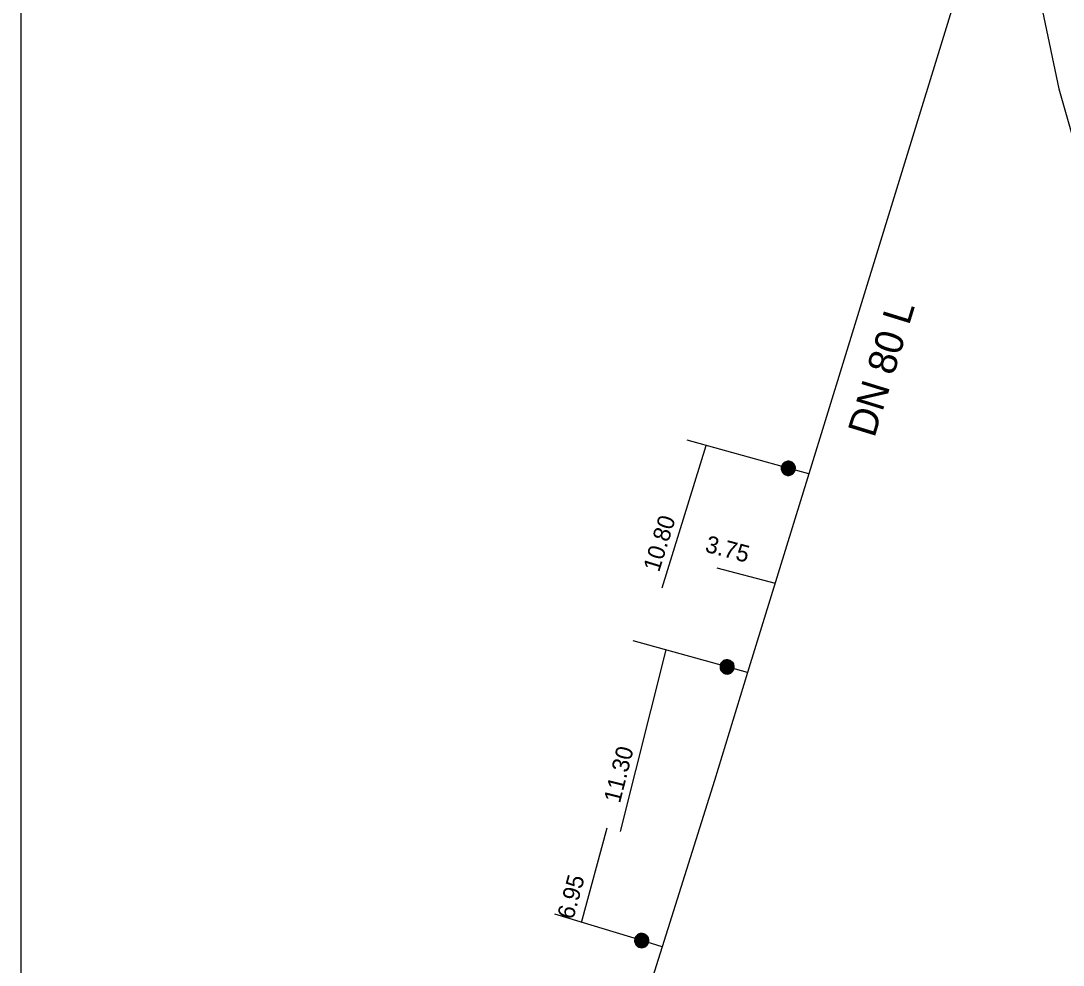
# Model space of a CAD drawing. Extents: x -820257 to -819974, y -1070894 to -1070484.
# Drawn here: x -820256.8 to -820183, y -1070688.6 to -1070621.8 of the extents above; entities that cross this region are included whole.
import ezdxf

# ---------------------------------------------------------------- set-up
doc = ezdxf.new("R2010")
doc.units = 0
for name, color, linetype in [('Default', 7, 'Continuous'), ('Oměrka vodovodu', 7, 'Continuous'), ('Oměrka-text', 7, 'Continuous'), ('Přípojka vodovodu', 7, 'Continuous'), ('Přípojkový uzávěr', 7, 'Continuous'), ('Roz-řad', 7, 'Continuous'), ('Roz-řad-popis základní', 7, 'Continuous')]:
    doc.layers.add(name, color=color, linetype=linetype)

msp = doc.modelspace()

# ---------------------------------------------------------------- linework, layer by layer
at = {"layer": 'Default'}
msp.add_lwpolyline([(-819975.603, -1070484.403), (-820256.81, -1070484.403), (-820256.81, -1070893.932)], dxfattribs=at)
at = {"layer": 'Oměrka vodovodu'}
for p, q in [((-820211.408, -1070661.903), (-820208.285, -1070651.83)), ((-820207.542, -1070660.475), (-820203.412, -1070661.564)), ((-820211.154, -1070666.294), (-820214.389, -1070679.146)), ((-820217.121, -1070685.573), (-820215.292, -1070678.876))]:
    msp.add_line(p, q, dxfattribs=at)
at = {"layer": 'Přípojka vodovodu'}
for points in [[(-820201.034, -1070653.842), (-820202.479, -1070653.441), (-820209.648, -1070651.452)], [(-820205.362, -1070667.895), (-820206.808, -1070667.495), (-820213.456, -1070665.657)], [(-820211.419, -1070687.296), (-820212.855, -1070686.862), (-820218.999, -1070685.006)]]:
    msp.add_lwpolyline(points, dxfattribs=at)
at = {"layer": 'Přípojkový uzávěr'}
for points in [[(-820202.345, -1070652.959), (-820202.224, -1070652.993), (-820202.126, -1070653.087), (-820202.028, -1070653.181), (-820201.995, -1070653.315), (-820201.962, -1070653.449), (-820201.997, -1070653.575), (-820202.032, -1070653.7), (-820202.127, -1070653.797), (-820202.222, -1070653.894), (-820202.355, -1070653.926), (-820202.487, -1070653.957), (-820202.613, -1070653.923), (-820202.737, -1070653.888), (-820202.835, -1070653.793), (-820202.932, -1070653.697), (-820202.963, -1070653.565), (-820202.995, -1070653.433), (-820202.96, -1070653.308), (-820202.925, -1070653.182), (-820202.829, -1070653.084), (-820202.732, -1070652.986), (-820202.599, -1070652.955), (-820202.467, -1070652.925), (-820202.345, -1070652.959)], [(-820202.358, -1070653.004), (-820202.468, -1070652.974), (-820202.588, -1070653.001), (-820202.708, -1070653.028), (-820202.796, -1070653.117), (-820202.884, -1070653.206), (-820202.915, -1070653.32), (-820202.947, -1070653.434), (-820202.918, -1070653.553), (-820202.89, -1070653.673), (-820202.801, -1070653.76), (-820202.713, -1070653.846), (-820202.6, -1070653.877), (-820202.486, -1070653.909), (-820202.366, -1070653.88), (-820202.246, -1070653.852), (-820202.16, -1070653.764), (-820202.073, -1070653.676), (-820202.042, -1070653.563), (-820202.01, -1070653.448), (-820202.04, -1070653.327), (-820202.07, -1070653.205), (-820202.159, -1070653.12), (-820202.248, -1070653.035), (-820202.358, -1070653.004)], [(-820202.367, -1070653.037), (-820202.265, -1070653.065), (-820202.183, -1070653.144), (-820202.101, -1070653.223), (-820202.073, -1070653.335), (-820202.046, -1070653.448), (-820202.075, -1070653.553), (-820202.104, -1070653.658), (-820202.184, -1070653.74), (-820202.263, -1070653.821), (-820202.374, -1070653.847), (-820202.486, -1070653.874), (-820202.591, -1070653.844), (-820202.695, -1070653.815), (-820202.777, -1070653.736), (-820202.859, -1070653.656), (-820202.885, -1070653.545), (-820202.911, -1070653.434), (-820202.882, -1070653.329), (-820202.853, -1070653.223), (-820202.772, -1070653.141), (-820202.691, -1070653.059), (-820202.58, -1070653.034), (-820202.469, -1070653.009), (-820202.367, -1070653.037)], [(-820202.379, -1070653.079), (-820202.53, -1070653.038), (-820202.664, -1070653.114), (-820202.798, -1070653.191), (-820202.84, -1070653.341), (-820202.882, -1070653.491), (-820202.805, -1070653.626), (-820202.728, -1070653.761), (-820202.58, -1070653.802), (-820202.429, -1070653.844), (-820202.294, -1070653.768), (-820202.159, -1070653.691), (-820202.117, -1070653.542), (-820202.076, -1070653.392), (-820202.151, -1070653.257), (-820202.227, -1070653.121), (-820202.379, -1070653.079)], [(-820202.391, -1070653.124), (-820202.259, -1070653.16), (-820202.193, -1070653.278), (-820202.127, -1070653.396), (-820202.163, -1070653.527), (-820202.199, -1070653.659), (-820202.318, -1070653.726), (-820202.436, -1070653.792), (-820202.567, -1070653.756), (-820202.699, -1070653.719), (-820202.765, -1070653.601), (-820202.832, -1070653.483), (-820202.795, -1070653.352), (-820202.759, -1070653.221), (-820202.641, -1070653.154), (-820202.523, -1070653.087), (-820202.391, -1070653.124)], [(-820202.402, -1070653.162), (-820202.518, -1070653.13), (-820202.622, -1070653.188), (-820202.725, -1070653.247), (-820202.757, -1070653.363), (-820202.789, -1070653.478), (-820202.731, -1070653.582), (-820202.672, -1070653.686), (-820202.556, -1070653.718), (-820202.441, -1070653.75), (-820202.337, -1070653.691), (-820202.233, -1070653.632), (-820202.201, -1070653.517), (-820202.169, -1070653.402), (-820202.227, -1070653.298), (-820202.286, -1070653.194), (-820202.402, -1070653.162)], [(-820202.412, -1070653.2), (-820202.311, -1070653.228), (-820202.26, -1070653.318), (-820202.21, -1070653.408), (-820202.238, -1070653.508), (-820202.265, -1070653.608), (-820202.356, -1070653.659), (-820202.446, -1070653.709), (-820202.546, -1070653.682), (-820202.645, -1070653.654), (-820202.696, -1070653.564), (-820202.747, -1070653.474), (-820202.72, -1070653.375), (-820202.692, -1070653.274), (-820202.602, -1070653.223), (-820202.513, -1070653.172), (-820202.412, -1070653.2)], [(-820202.425, -1070653.245), (-820202.506, -1070653.222), (-820202.579, -1070653.263), (-820202.652, -1070653.305), (-820202.675, -1070653.386), (-820202.697, -1070653.467), (-820202.656, -1070653.54), (-820202.615, -1070653.613), (-820202.533, -1070653.636), (-820202.452, -1070653.659), (-820202.379, -1070653.617), (-820202.306, -1070653.576), (-820202.283, -1070653.495), (-820202.261, -1070653.413), (-820202.302, -1070653.34), (-820202.343, -1070653.267), (-820202.425, -1070653.245)], [(-820202.434, -1070653.278), (-820202.366, -1070653.297), (-820202.332, -1070653.357), (-820202.298, -1070653.418), (-820202.317, -1070653.485), (-820202.335, -1070653.553), (-820202.396, -1070653.587), (-820202.457, -1070653.621), (-820202.524, -1070653.603), (-820202.592, -1070653.584), (-820202.626, -1070653.523), (-820202.66, -1070653.463), (-820202.641, -1070653.395), (-820202.622, -1070653.328), (-820202.562, -1070653.293), (-820202.502, -1070653.259), (-820202.434, -1070653.278)], [(-820202.446, -1070653.32), (-820202.495, -1070653.306), (-820202.54, -1070653.332), (-820202.585, -1070653.358), (-820202.599, -1070653.407), (-820202.613, -1070653.457), (-820202.587, -1070653.502), (-820202.562, -1070653.548), (-820202.512, -1070653.561), (-820202.462, -1070653.575), (-820202.417, -1070653.55), (-820202.372, -1070653.524), (-820202.358, -1070653.474), (-820202.344, -1070653.424), (-820202.369, -1070653.379), (-820202.395, -1070653.334), (-820202.446, -1070653.32)], [(-820202.458, -1070653.366), (-820202.426, -1070653.374), (-820202.41, -1070653.402), (-820202.395, -1070653.43), (-820202.404, -1070653.462), (-820202.412, -1070653.493), (-820202.44, -1070653.509), (-820202.468, -1070653.525), (-820202.5, -1070653.516), (-820202.531, -1070653.507), (-820202.547, -1070653.479), (-820202.563, -1070653.451), (-820202.554, -1070653.42), (-820202.545, -1070653.388), (-820202.517, -1070653.372), (-820202.489, -1070653.357), (-820202.458, -1070653.366)], [(-820202.466, -1070653.396), (-820202.485, -1070653.39), (-820202.502, -1070653.4), (-820202.519, -1070653.409), (-820202.524, -1070653.428), (-820202.529, -1070653.447), (-820202.52, -1070653.464), (-820202.51, -1070653.481), (-820202.492, -1070653.486), (-820202.472, -1070653.491), (-820202.456, -1070653.482), (-820202.439, -1070653.472), (-820202.434, -1070653.453), (-820202.428, -1070653.434), (-820202.438, -1070653.418), (-820202.447, -1070653.401), (-820202.466, -1070653.396)], [(-820206.675, -1070667.013), (-820206.554, -1070667.047), (-820206.456, -1070667.141), (-820206.357, -1070667.235), (-820206.324, -1070667.369), (-820206.291, -1070667.503), (-820206.326, -1070667.629), (-820206.361, -1070667.754), (-820206.456, -1070667.851), (-820206.551, -1070667.948), (-820206.683, -1070667.98), (-820206.816, -1070668.012), (-820206.942, -1070667.977), (-820207.066, -1070667.943), (-820207.164, -1070667.847), (-820207.261, -1070667.752), (-820207.293, -1070667.62), (-820207.324, -1070667.488), (-820207.29, -1070667.363), (-820207.255, -1070667.236), (-820207.158, -1070667.138), (-820207.061, -1070667.04), (-820206.929, -1070667.01), (-820206.797, -1070666.98), (-820206.675, -1070667.013)], [(-820206.688, -1070667.058), (-820206.798, -1070667.028), (-820206.918, -1070667.055), (-820207.038, -1070667.083), (-820207.125, -1070667.172), (-820207.213, -1070667.261), (-820207.245, -1070667.375), (-820207.276, -1070667.488), (-820207.247, -1070667.608), (-820207.219, -1070667.728), (-820207.13, -1070667.814), (-820207.042, -1070667.901), (-820206.929, -1070667.932), (-820206.815, -1070667.963), (-820206.695, -1070667.935), (-820206.575, -1070667.906), (-820206.489, -1070667.818), (-820206.403, -1070667.73), (-820206.371, -1070667.617), (-820206.34, -1070667.502), (-820206.37, -1070667.381), (-820206.4, -1070667.259), (-820206.489, -1070667.174), (-820206.577, -1070667.089), (-820206.688, -1070667.058)], [(-820206.697, -1070667.091), (-820206.595, -1070667.12), (-820206.513, -1070667.198), (-820206.431, -1070667.277), (-820206.403, -1070667.389), (-820206.375, -1070667.502), (-820206.404, -1070667.607), (-820206.433, -1070667.712), (-820206.513, -1070667.794), (-820206.592, -1070667.875), (-820206.703, -1070667.902), (-820206.815, -1070667.928), (-820206.92, -1070667.899), (-820207.024, -1070667.87), (-820207.106, -1070667.79), (-820207.188, -1070667.71), (-820207.214, -1070667.6), (-820207.241, -1070667.489), (-820207.212, -1070667.384), (-820207.182, -1070667.278), (-820207.101, -1070667.196), (-820207.021, -1070667.114), (-820206.909, -1070667.089), (-820206.798, -1070667.063), (-820206.697, -1070667.091)], [(-820206.709, -1070667.134), (-820206.859, -1070667.092), (-820206.994, -1070667.169), (-820207.128, -1070667.246), (-820207.169, -1070667.396), (-820207.211, -1070667.546), (-820207.134, -1070667.68), (-820207.057, -1070667.815), (-820206.909, -1070667.857), (-820206.758, -1070667.898), (-820206.623, -1070667.822), (-820206.488, -1070667.745), (-820206.447, -1070667.596), (-820206.405, -1070667.446), (-820206.481, -1070667.311), (-820206.557, -1070667.176), (-820206.709, -1070667.134)], [(-820206.721, -1070667.178), (-820206.589, -1070667.214), (-820206.522, -1070667.332), (-820206.456, -1070667.45), (-820206.492, -1070667.582), (-820206.529, -1070667.713), (-820206.647, -1070667.78), (-820206.765, -1070667.847), (-820206.896, -1070667.81), (-820207.028, -1070667.774), (-820207.094, -1070667.656), (-820207.161, -1070667.538), (-820207.125, -1070667.407), (-820207.088, -1070667.275), (-820206.971, -1070667.208), (-820206.853, -1070667.141), (-820206.721, -1070667.178)], [(-820206.732, -1070667.216), (-820206.847, -1070667.184), (-820206.951, -1070667.243), (-820207.055, -1070667.302), (-820207.087, -1070667.417), (-820207.119, -1070667.533), (-820207.06, -1070667.636), (-820207.001, -1070667.74), (-820206.885, -1070667.772), (-820206.77, -1070667.804), (-820206.666, -1070667.745), (-820206.562, -1070667.686), (-820206.53, -1070667.571), (-820206.499, -1070667.456), (-820206.557, -1070667.352), (-820206.615, -1070667.248), (-820206.732, -1070667.216)], [(-820206.742, -1070667.254), (-820206.641, -1070667.282), (-820206.59, -1070667.372), (-820206.539, -1070667.462), (-820206.567, -1070667.562), (-820206.595, -1070667.662), (-820206.685, -1070667.713), (-820206.775, -1070667.764), (-820206.875, -1070667.736), (-820206.974, -1070667.709), (-820207.025, -1070667.619), (-820207.077, -1070667.529), (-820207.049, -1070667.429), (-820207.021, -1070667.329), (-820206.932, -1070667.278), (-820206.842, -1070667.226), (-820206.742, -1070667.254)], [(-820206.754, -1070667.299), (-820206.835, -1070667.276), (-820206.908, -1070667.318), (-820206.981, -1070667.359), (-820207.004, -1070667.441), (-820207.026, -1070667.522), (-820206.985, -1070667.595), (-820206.944, -1070667.668), (-820206.862, -1070667.691), (-820206.781, -1070667.713), (-820206.708, -1070667.672), (-820206.635, -1070667.63), (-820206.612, -1070667.549), (-820206.59, -1070667.467), (-820206.631, -1070667.394), (-820206.673, -1070667.321), (-820206.754, -1070667.299)], [(-820206.763, -1070667.332), (-820206.696, -1070667.351), (-820206.661, -1070667.411), (-820206.627, -1070667.472), (-820206.646, -1070667.54), (-820206.665, -1070667.607), (-820206.725, -1070667.642), (-820206.786, -1070667.676), (-820206.853, -1070667.657), (-820206.921, -1070667.638), (-820206.955, -1070667.578), (-820206.989, -1070667.518), (-820206.971, -1070667.45), (-820206.952, -1070667.382), (-820206.891, -1070667.348), (-820206.831, -1070667.314), (-820206.763, -1070667.332)], [(-820206.775, -1070667.375), (-820206.825, -1070667.361), (-820206.87, -1070667.387), (-820206.915, -1070667.412), (-820206.928, -1070667.462), (-820206.942, -1070667.512), (-820206.917, -1070667.557), (-820206.891, -1070667.602), (-820206.842, -1070667.616), (-820206.791, -1070667.63), (-820206.746, -1070667.604), (-820206.701, -1070667.579), (-820206.687, -1070667.529), (-820206.674, -1070667.479), (-820206.699, -1070667.434), (-820206.724, -1070667.389), (-820206.775, -1070667.375)], [(-820206.787, -1070667.42), (-820206.755, -1070667.429), (-820206.74, -1070667.456), (-820206.724, -1070667.484), (-820206.733, -1070667.516), (-820206.742, -1070667.547), (-820206.769, -1070667.563), (-820206.797, -1070667.579), (-820206.829, -1070667.57), (-820206.86, -1070667.562), (-820206.876, -1070667.534), (-820206.892, -1070667.505), (-820206.884, -1070667.474), (-820206.875, -1070667.442), (-820206.847, -1070667.427), (-820206.819, -1070667.411), (-820206.787, -1070667.42)], [(-820206.796, -1070667.45), (-820206.815, -1070667.445), (-820206.831, -1070667.454), (-820206.848, -1070667.463), (-820206.853, -1070667.483), (-820206.859, -1070667.502), (-820206.849, -1070667.518), (-820206.84, -1070667.535), (-820206.821, -1070667.54), (-820206.802, -1070667.546), (-820206.785, -1070667.536), (-820206.768, -1070667.527), (-820206.763, -1070667.508), (-820206.758, -1070667.488), (-820206.767, -1070667.472), (-820206.777, -1070667.455), (-820206.796, -1070667.45)], [(-820212.711, -1070686.383), (-820212.59, -1070686.42), (-820212.494, -1070686.516), (-820212.398, -1070686.612), (-820212.368, -1070686.747), (-820212.338, -1070686.882), (-820212.376, -1070687.007), (-820212.414, -1070687.131), (-820212.511, -1070687.226), (-820212.609, -1070687.321), (-820212.742, -1070687.35), (-820212.875, -1070687.378), (-820213, -1070687.34), (-820213.124, -1070687.303), (-820213.219, -1070687.205), (-820213.314, -1070687.108), (-820213.342, -1070686.975), (-820213.371, -1070686.842), (-820213.334, -1070686.718), (-820213.296, -1070686.593), (-820213.197, -1070686.497), (-820213.098, -1070686.401), (-820212.965, -1070686.374), (-820212.832, -1070686.347), (-820212.711, -1070686.383)], [(-820212.724, -1070686.428), (-820212.834, -1070686.395), (-820212.954, -1070686.42), (-820213.075, -1070686.444), (-820213.165, -1070686.531), (-820213.254, -1070686.618), (-820213.289, -1070686.731), (-820213.323, -1070686.844), (-820213.297, -1070686.964), (-820213.271, -1070687.085), (-820213.185, -1070687.173), (-820213.098, -1070687.262), (-820212.986, -1070687.296), (-820212.873, -1070687.33), (-820212.752, -1070687.304), (-820212.632, -1070687.278), (-820212.543, -1070687.192), (-820212.455, -1070687.106), (-820212.421, -1070686.994), (-820212.387, -1070686.88), (-820212.414, -1070686.758), (-820212.441, -1070686.635), (-820212.528, -1070686.548), (-820212.615, -1070686.461), (-820212.724, -1070686.428)], [(-820212.734, -1070686.461), (-820212.633, -1070686.491), (-820212.553, -1070686.572), (-820212.473, -1070686.653), (-820212.447, -1070686.765), (-820212.422, -1070686.878), (-820212.454, -1070686.984), (-820212.485, -1070687.088), (-820212.567, -1070687.167), (-820212.648, -1070687.247), (-820212.76, -1070687.271), (-820212.872, -1070687.295), (-820212.976, -1070687.263), (-820213.08, -1070687.232), (-820213.16, -1070687.15), (-820213.24, -1070687.068), (-820213.264, -1070686.957), (-820213.287, -1070686.846), (-820213.256, -1070686.741), (-820213.224, -1070686.636), (-820213.141, -1070686.556), (-820213.058, -1070686.476), (-820212.947, -1070686.453), (-820212.835, -1070686.43), (-820212.734, -1070686.461)], [(-820212.747, -1070686.503), (-820212.897, -1070686.458), (-820213.033, -1070686.531), (-820213.169, -1070686.605), (-820213.214, -1070686.754), (-820213.259, -1070686.903), (-820213.185, -1070687.039), (-820213.112, -1070687.176), (-820212.964, -1070687.221), (-820212.815, -1070687.266), (-820212.678, -1070687.193), (-820212.541, -1070687.12), (-820212.496, -1070686.971), (-820212.451, -1070686.822), (-820212.524, -1070686.685), (-820212.596, -1070686.548), (-820212.747, -1070686.503)], [(-820212.761, -1070686.547), (-820212.629, -1070686.586), (-820212.566, -1070686.706), (-820212.502, -1070686.825), (-820212.541, -1070686.956), (-820212.581, -1070687.086), (-820212.7, -1070687.15), (-820212.82, -1070687.214), (-820212.95, -1070687.175), (-820213.081, -1070687.135), (-820213.145, -1070687.016), (-820213.209, -1070686.896), (-820213.17, -1070686.766), (-820213.13, -1070686.635), (-820213.011, -1070686.571), (-820212.891, -1070686.507), (-820212.761, -1070686.547)], [(-820212.772, -1070686.585), (-820212.887, -1070686.55), (-820212.992, -1070686.606), (-820213.097, -1070686.663), (-820213.132, -1070686.777), (-820213.166, -1070686.892), (-820213.11, -1070686.997), (-820213.054, -1070687.102), (-820212.939, -1070687.137), (-820212.824, -1070687.172), (-820212.719, -1070687.115), (-820212.614, -1070687.059), (-820212.579, -1070686.944), (-820212.545, -1070686.83), (-820212.601, -1070686.725), (-820212.656, -1070686.619), (-820212.772, -1070686.585)], [(-820212.783, -1070686.623), (-820212.682, -1070686.653), (-820212.634, -1070686.744), (-820212.586, -1070686.835), (-820212.616, -1070686.935), (-820212.646, -1070687.034), (-820212.737, -1070687.083), (-820212.828, -1070687.131), (-820212.928, -1070687.101), (-820213.026, -1070687.071), (-820213.075, -1070686.98), (-820213.124, -1070686.889), (-820213.094, -1070686.79), (-820213.064, -1070686.691), (-820212.974, -1070686.641), (-820212.883, -1070686.592), (-820212.783, -1070686.623)], [(-820212.796, -1070686.667), (-820212.877, -1070686.643), (-820212.951, -1070686.682), (-820213.025, -1070686.722), (-820213.05, -1070686.803), (-820213.074, -1070686.883), (-820213.034, -1070686.957), (-820212.995, -1070687.031), (-820212.914, -1070687.056), (-820212.833, -1070687.08), (-820212.759, -1070687.041), (-820212.685, -1070687.001), (-820212.661, -1070686.92), (-820212.636, -1070686.839), (-820212.676, -1070686.765), (-820212.715, -1070686.691), (-820212.796, -1070686.667)], [(-820212.806, -1070686.7), (-820212.739, -1070686.72), (-820212.706, -1070686.782), (-820212.673, -1070686.843), (-820212.694, -1070686.91), (-820212.714, -1070686.977), (-820212.776, -1070687.01), (-820212.837, -1070687.043), (-820212.904, -1070687.023), (-820212.971, -1070687.002), (-820213.004, -1070686.941), (-820213.037, -1070686.88), (-820213.016, -1070686.813), (-820212.996, -1070686.745), (-820212.935, -1070686.713), (-820212.874, -1070686.68), (-820212.806, -1070686.7)], [(-820212.819, -1070686.742), (-820212.869, -1070686.727), (-820212.914, -1070686.752), (-820212.959, -1070686.776), (-820212.974, -1070686.826), (-820212.989, -1070686.875), (-820212.965, -1070686.921), (-820212.94, -1070686.967), (-820212.891, -1070686.982), (-820212.841, -1070686.997), (-820212.796, -1070686.972), (-820212.75, -1070686.948), (-820212.735, -1070686.898), (-820212.72, -1070686.849), (-820212.744, -1070686.803), (-820212.769, -1070686.757), (-820212.819, -1070686.742)], [(-820212.833, -1070686.787), (-820212.801, -1070686.797), (-820212.786, -1070686.825), (-820212.771, -1070686.853), (-820212.78, -1070686.884), (-820212.79, -1070686.915), (-820212.818, -1070686.931), (-820212.846, -1070686.946), (-820212.878, -1070686.937), (-820212.909, -1070686.927), (-820212.924, -1070686.899), (-820212.939, -1070686.87), (-820212.93, -1070686.839), (-820212.92, -1070686.807), (-820212.892, -1070686.793), (-820212.863, -1070686.778), (-820212.833, -1070686.787)], [(-820212.842, -1070686.817), (-820212.86, -1070686.811), (-820212.877, -1070686.82), (-820212.894, -1070686.829), (-820212.9, -1070686.848), (-820212.906, -1070686.867), (-820212.897, -1070686.884), (-820212.887, -1070686.901), (-820212.869, -1070686.907), (-820212.85, -1070686.913), (-820212.833, -1070686.903), (-820212.816, -1070686.894), (-820212.81, -1070686.875), (-820212.805, -1070686.856), (-820212.814, -1070686.84), (-820212.823, -1070686.823), (-820212.842, -1070686.817)]]:
    msp.add_open_spline(points, degree=3, dxfattribs=at)
at = {"layer": 'Roz-řad'}
for points in [[(-820192.294, -1070583.934), (-820183.322, -1070626.593), (-820174.41, -1070657.75)], [(-820190.84, -1070620.738), (-820198.53, -1070645.709), (-820201.034, -1070653.842), (-820205.362, -1070667.895), (-820207.714, -1070675.535), (-820211.419, -1070687.296), (-820213.068, -1070692.533), (-820218.767, -1070711.114)]]:
    msp.add_lwpolyline(points, dxfattribs=at)

# ---------------------------------------------------------------- texts
at = {"layer": 'Oměrka-text'}
for s, rotation, p in [('10.80', 72.77464, (-820211.632, -1070660.841)), (' 3.75', 345.22844, (-820208.867, -1070659.218)), ('11.30', 75.87147, (-820214.397, -1070677.194)), (' 6.95', 74.72464, (-820217.822, -1070685.851))]:
    msp.add_text(s, height=1.2, rotation=rotation, dxfattribs=at).set_placement(p)
at = {"layer": 'Roz-řad-popis základní'}
msp.add_text('DN 80 L', height=2, rotation=72.88539, dxfattribs=at).set_placement((-820196.388, -1070651.333))

doc.saveas('drawing.dxf')
